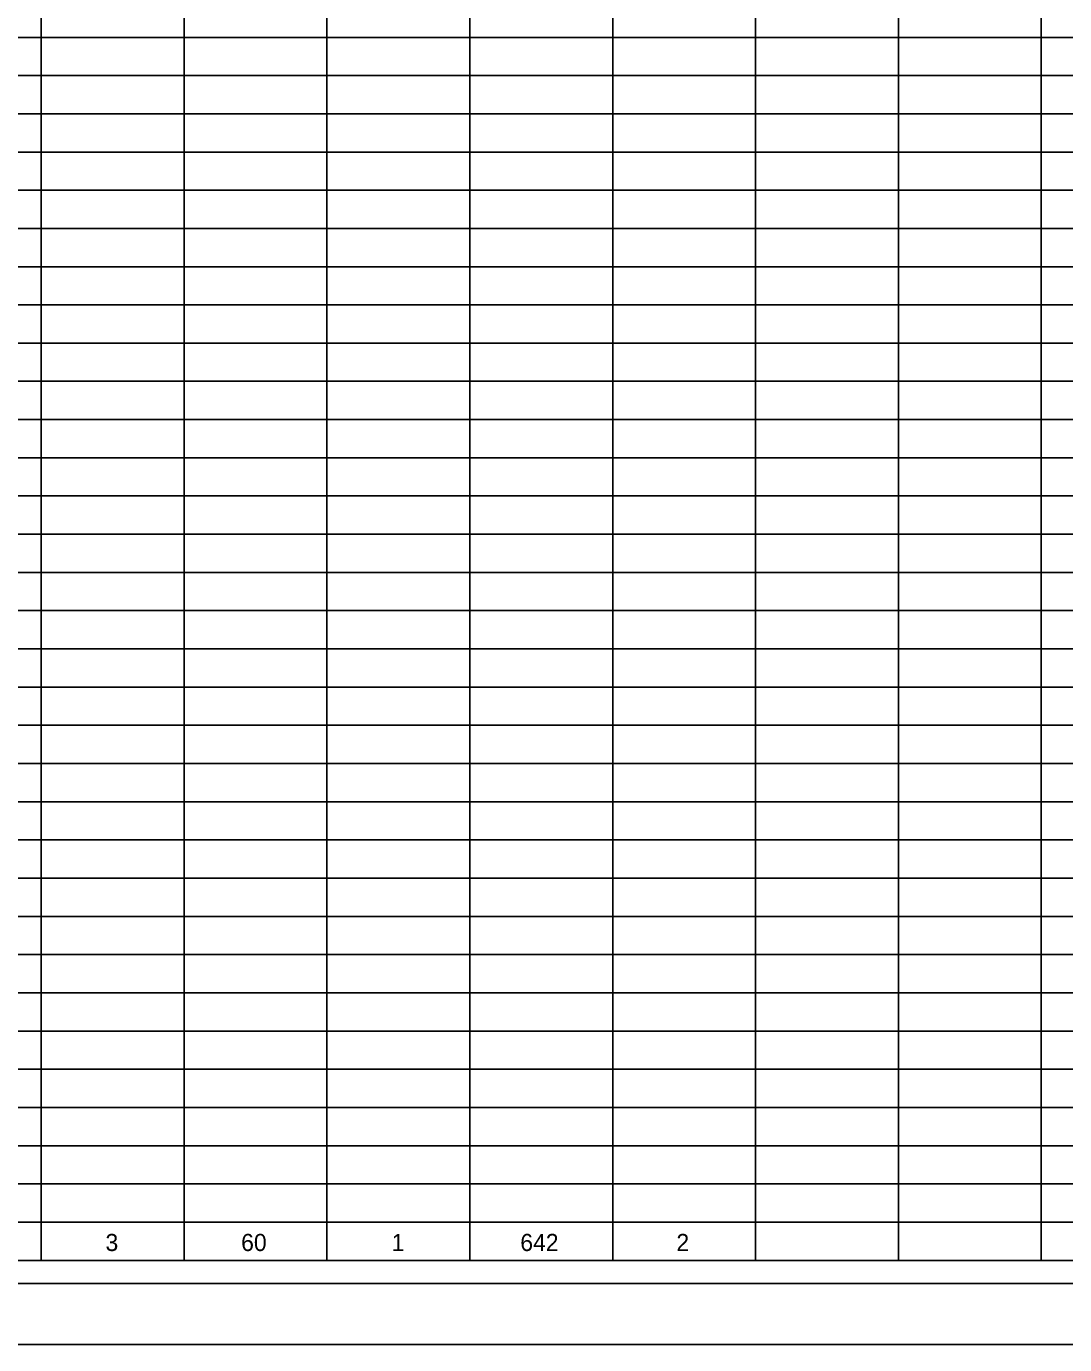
# Model space of a CAD drawing. Extents: x 0 to 34, y 0 to 22.
# Drawn here: x 17.05 to 25.53, y 0 to 10.76 of the extents above; entities that cross this region are included whole.
import ezdxf

# ---------------------------------------------------------------- set-up
doc = ezdxf.new("R2010")
doc.units = 0
for name, color, linetype in [('Default', 7, 'Continuous'), ('SH_Border', 7, 'Continuous'), ('SH_Cut_Line', 7, 'Continuous'), ('SH_Data', 7, 'Continuous')]:
    doc.layers.add(name, color=color, linetype=linetype)

msp = doc.modelspace()

# ---------------------------------------------------------------- linework, layer by layer
at = {"layer": 'Default'}
for p, q in [((31.167, 10.672), (1.5, 10.672)), ((31.167, 10.36), (1.5, 10.36)), ((31.167, 10.048), (1.5, 10.048)), ((31.167, 9.736), (1.5, 9.736)), ((31.167, 9.424), (1.5, 9.424)), ((31.167, 9.112), (1.5, 9.112)), ((31.167, 8.8), (1.5, 8.8)), ((31.167, 8.488), (1.5, 8.488)), ((31.167, 8.176), (1.5, 8.176)), ((31.167, 7.864), (1.5, 7.864)), ((31.167, 7.552), (1.5, 7.552)), ((31.167, 7.24), (1.5, 7.24)), ((31.167, 6.928), (1.5, 6.928)), ((31.167, 6.616), (1.5, 6.616)), ((31.167, 6.304), (1.5, 6.304)), ((31.167, 5.992), (1.5, 5.992)), ((31.167, 5.68), (1.5, 5.68)), ((31.167, 5.368), (1.5, 5.368)), ((31.167, 5.056), (1.5, 5.056)), ((31.167, 4.744), (1.5, 4.744)), ((31.167, 4.432), (1.5, 4.432)), ((31.167, 4.12), (1.5, 4.12)), ((31.167, 3.808), (1.5, 3.808)), ((31.167, 3.496), (1.5, 3.496)), ((31.167, 3.184), (1.5, 3.184)), ((31.167, 2.872), (1.5, 2.872)), ((31.167, 2.56), (1.5, 2.56)), ((31.167, 2.248), (1.5, 2.248)), ((31.167, 1.936), (1.5, 1.936)), ((31.167, 1.624), (1.5, 1.624)), ((31.167, 1.312), (1.5, 1.312))]:
    msp.add_line(p, q, dxfattribs=at)
at = {"layer": 'SH_Border'}
msp.add_lwpolyline([(1.5, 21.5), (33.5, 21.5), (33.5, 0.5), (1.5, 0.5)], close=True, dxfattribs=at)
at = {"layer": 'SH_Cut_Line'}
msp.add_lwpolyline([(0, 0), (34, 0), (34, 22), (0, 22)], close=True, dxfattribs=at)
at = {"layer": 'SH_Data'}
for p, q in [((18.341, 21.498), (18.341, 0.686)), ((20.673, 21.5), (20.673, 0.688)), ((21.839, 21.5), (21.839, 0.688)), ((21.839, 21.5), (21.839, 0.688)), ((21.839, 21.5), (21.839, 0.688)), ((21.839, 21.498), (21.839, 0.686)), ((23.005, 21.5), (23.005, 0.688)), ((24.171, 21.5), (24.171, 0.688)), ((25.337, 21.5), (25.337, 0.688)), ((17.175, 21.188), (17.175, 0.688)), ((18.341, 21.188), (18.341, 0.688)), ((18.341, 21.188), (18.341, 0.688)), ((18.341, 21.188), (18.341, 0.688)), ((19.507, 21.188), (19.507, 0.688)), ((20.673, 21.188), (20.673, 0.688)), ((31.167, 1), (1.5, 1)), ((31.167, 0.688), (1.5, 0.688))]:
    msp.add_line(p, q, dxfattribs=at)

# ---------------------------------------------------------------- texts
for s, p in [('3', (17.7, 0.764)), ('60', (18.807, 0.764)), ('1', (20.035, 0.764)), ('642', (21.085, 0.764)), ('2', (22.359, 0.764))]:
    msp.add_text(s, height=0.14, dxfattribs=at).set_placement(p)

doc.saveas('drawing.dxf')
